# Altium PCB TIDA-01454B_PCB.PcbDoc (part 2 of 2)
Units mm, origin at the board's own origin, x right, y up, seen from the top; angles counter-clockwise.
Board outline 75 x 75 mm, 6 copper layers (Top Copper, Copper Layer 2, Copper Layer 3, Copper Layer 4, Copper Layer 5, Bottom Copper), stack 1.56 mm thick; 207 components, 118 nets, 481 pads, 110 vias.
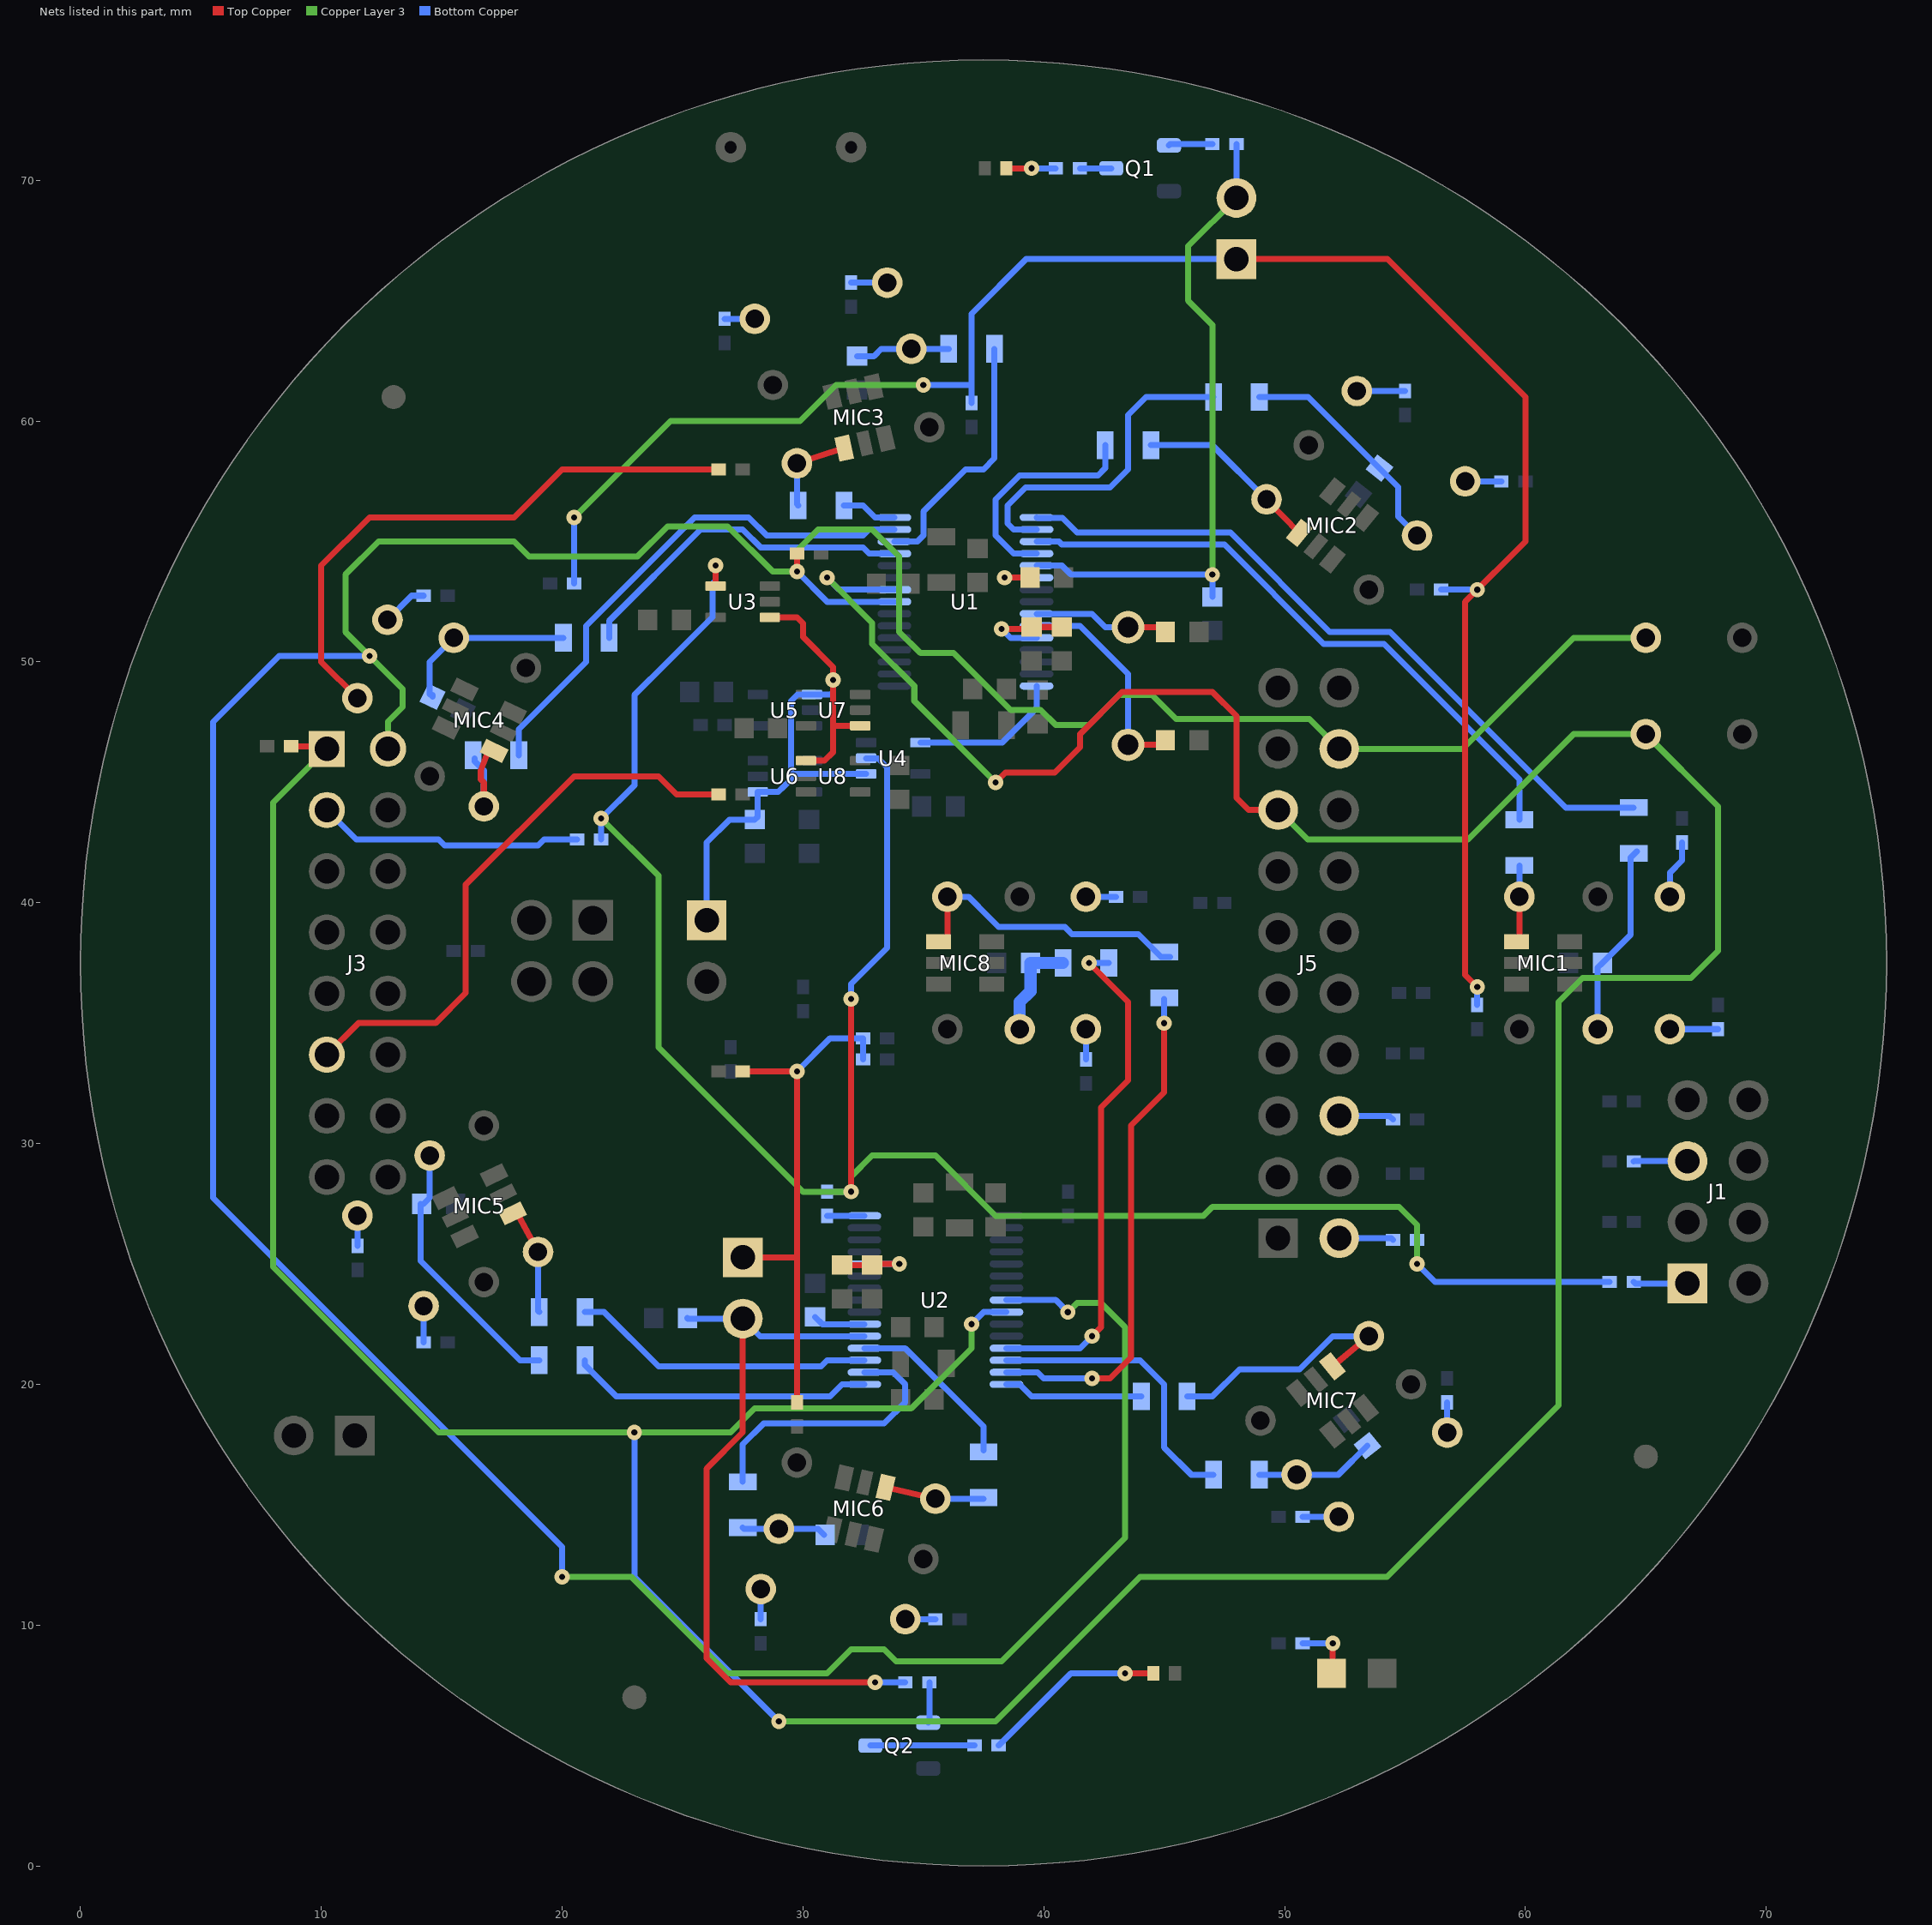
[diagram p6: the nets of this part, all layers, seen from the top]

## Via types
v1: diameter 0.635, hole 0.254, Top Copper to Bottom Copper, tented both sides, 98 vias
v2: diameter 0.762, hole 0.381, Top Copper to Bottom Copper, 7 vias
v3: diameter 6, hole 3.25, Top Copper to Bottom Copper, tented both sides, 4 vias
v4: diameter 0.75, hole 0.38, Top Copper to Bottom Copper, 1 vias

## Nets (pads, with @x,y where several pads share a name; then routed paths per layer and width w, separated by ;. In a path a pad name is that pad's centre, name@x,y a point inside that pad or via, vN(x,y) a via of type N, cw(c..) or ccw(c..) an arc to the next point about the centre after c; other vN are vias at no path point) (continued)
LRCLK-I2X: J3.11 R6.2 | length 24
  Top Copper w0.25: J3.11@10.23,33.69 11.54,35 14.75,35 16,36.25 16,40.75 20.5,45.25 24,45.25 24.75,44.5 R6.2@26.5,44.5
LRCLK-MINIDSP: J5.6 R16.2 | length 2.3
  Bottom Copper w0.25: J5.6@52.27,31.15 54.35,31.15 R16.2@54.5,31
LRCLK-PSIA: J1.5 R3.2 | length 2.2
  Bottom Copper w0.25: R3.2@64.5,29.25 64.52,29.27 J1.5@66.73,29.27
MCLK-I2X: J3.3 R9.2 | length 11.1
  Bottom Copper w0.25: J3.3@10.23,43.85 11.455,42.625 14.875,42.625 15.125,42.375 19,42.375 19.25,42.625 R9.2@20.625,42.625
MCLK-MINIDSP: J5.2 R12.2 | length 2.3
  Bottom Copper w0.25: J5.2@52.27,26.07 54.43,26.07 R12.2@54.5,26
MCLK-PSIA: J1.1 R1.2 | length 2.3
  Bottom Copper w0.25: R1.2@64.5,24.25 64.56,24.19 J1.1@66.73,24.19
MICBIAS-A: C23.2 J7.2 R47.2 U1.5 | length 27.5
  Copper Layer 3 w0.25: v1(47,53.625) 47,64 46,65 46,67.27 J7.2@48,69.27
  Bottom Copper w0.25: U1.5@39.7,54 40.75,54 41.125,53.625 v1(47,53.625) C23.2@47,52.7 ; J7.2@48,69.27 R47.2@48,71.5
MICBIAS-B: C37.2 J8.2 R58.2 U2.5 | length 31.1
  Top Copper w0.25: J8.2@27.5,22.73 27.5,18 26,16.5 26,8.625 27,7.625 v1(33,7.625)
  Bottom Copper w0.25: C37.2@25.2,22.75 25.22,22.73 J8.2@27.5,22.73 28.23,22 U2.5@32.55,22 ; v1(33,7.625) R58.2@34.25,7.625
NetC9_2: C9.2 MIC1.4 TP11.1 | length 3.2
  Top Copper w0.25: MIC1.4@59.634,38.384 59.75,38.5 TP11.1@59.75,40.25
  Bottom Copper w0.25: TP11.1@59.75,40.25 C9.2@59.75,41.55
NetC10_2: C10.2 MIC2.4 TP12.1 | length 7.7
  Top Copper w0.25: TP12.1@49.25,56.75 MIC2.4@50.609,55.356
  Bottom Copper w0.25: C10.2@44.45,59 47,59 TP12.1@49.25,56.75
NetC11_2: C11.2 MIC3.4 TP13.1 | length 3.8
  Top Copper w0.25: TP13.1@29.75,58.25 MIC3.4@31.713,58.882
  Bottom Copper w0.25: TP13.1@29.75,58.25 29.75,56.55 C11.2@29.8,56.5
NetC12_2: C12.2 MIC4.4 TP14.1 | length 5
  Top Copper w0.25: TP14.1@16.75,44 16.75,45 16.625,45.125 16.625,45.5 16.958,46.388 17,46.5 MIC4.4@17.174,46.307
  Bottom Copper w0.25: C12.2@16.375,46 16.375,45.875 16.75,45.5 TP14.1@16.75,44
NetC13_2: C13.2 R23.1 TP15.1 | length 8
  Bottom Copper w0.25: TP15.1@63,34.75 63,37.3 R23.1@63.2,37.5 64.375,38.675 64.375,41.875 C13.2@64.625,42.125
NetC14_2: C14.2 R24.1 TP16.1 | length 9.7
  Bottom Copper w0.25: C14.2@48.95,61 50.984,61 R24.1@53.936,58.047 54.718,57.266 54.718,56.032 TP16.1@55.5,55.25
NetC15_2: C15.2 R25.1 TP17.1 | length 3.9
  Bottom Copper w0.25: R25.1@32.25,62.7 32.95,62.7 33.25,63 TP17.1@34.5,63 C15.2@36.05,63
NetC16_2: C16.2 R26.1 TP18.1 | length 7.5
  Bottom Copper w0.25: R26.1@14.619,48.619 R26.1@14.619,48.554 14.5,48.673 14.5,50 TP18.1@15.5,51 C16.2@20.05,51
NetC19_2: C19.2 MIC5.4 TP35.1 | length 4.6
  Top Copper w0.25: MIC5.4@17.942,27.099 18.125,27.125 TP35.1@19,25.5
  Bottom Copper w0.25: TP35.1@19,25.5 19,23.05 C19.2@19.05,23
NetC20_2: C20.2 MIC6.4 TP36.1 | length 4.1
  Top Copper w0.25: MIC6.4@33.437,15.724 TP36.1@35.5,15.25
  Bottom Copper w0.25: TP36.1@35.5,15.25 C20.2@37.5,15.25
NetC21_2: C21.2 MIC7.4 TP37.1 | length 10.5
  Top Copper w0.25: MIC7.4@51.992,20.747 TP37.1@53.5,22
  Bottom Copper w0.25: C21.2@45.95,19.5 47,19.5 48.125,20.625 50.625,20.625 52,22 TP37.1@53.5,22
NetC22_2: C22.2 MIC8.4 TP38.1 | length 12.5
  Top Copper w0.25: MIC8.4@35.634,38.384 35.991,38.384 36,38.375 TP38.1@36,40.25
  Bottom Copper w0.25: TP38.1@36,40.25 36.875,40.25 37.75,39.375 38.125,39 40.875,39 41,38.875 41.175,38.7 43.925,38.7 44.875,37.75 C22.2@45.25,37.75
NetC24_1: C24.1 U1.6 | length 2.4
  Top Copper w0.25: v1(38.375,53.5) C24.1@39.425,53.5 C24.1@39.5,53.5
  Bottom Copper w0.25: v1(38.375,53.5) U1.6@39.7,53.5
NetC25_2: C25.2 C26.1 U1.11 | length 4.1
  Top Copper w0.25: v1(38.25,51.375) 39.425,51.375 C25.2@39.5,51.45 C26.1@40.75,51.45
  Bottom Copper w0.25: v1(38.25,51.375) 38.625,51 U1.11@39.7,51
NetC27_1: C27.1 U1.9 Y1.1 | length 5.6
  Top Copper w0.25: Y1.1@43.5,51.44 44.81,51.44 C27.1@45,51.25
  Bottom Copper w0.25: U1.9@39.7,52 42,52 42.56,51.44 Y1.1@43.5,51.44
NetC28_1: C28.1 U1.10 Y1.2 | length 9.6
  Top Copper w0.25: Y1.2@43.5,46.56 44.81,46.56 C28.1@45.25,47
  Bottom Copper w0.25: U1.10@39.7,51.5 41.5,51.5 43.5,49.5 Y1.2@43.5,46.56 Y1.2@43.5,46.5
NetC33_2: C33.2 R32.1 TP39.1 | length 11.1
  Bottom Copper w0.25: R32.1@14.125,27.5 14.125,25.125 18.25,21 C33.2@19.05,21 ; R32.1@14.25,27.5 14.5,27.75 TP39.1@14.5,29.5
NetC34_2: C34.2 R33.1 TP40.1 | length 3.5
  Bottom Copper w0.25: C34.2@27.5,14.05 27.55,14 TP40.1@29,14 30.625,14 R33.1@30.875,13.75
NetC35_2: C35.2 R34.1 TP41.1 | length 5
  Bottom Copper w0.25: C35.2@48.95,16.25 TP41.1@50.5,16.25 52.234,16.25 R34.1@53.436,17.453
NetC36_2: C36.2 R35.1 TP42.1 | length 4.3
  Bottom Copper w0.5: TP42.1@39,34.75 39,35.875 39.45,36.325 R35.1@39.45,37.5 C36.2@40.8,37.5
NetC38_1: C38.1 U2.6 | length 2.2
  Bottom Copper w0.25: C38.1@30.5,22.8 30.8,22.5 U2.6@32.55,22.5
NetC39_2: C39.2 C40.1 U2.11 | length 3.8
  Top Copper w0.25: C40.1@31.625,24.95 C39.2@32.875,24.95 32.925,25 v1(34,25)
  Bottom Copper w0.25: U2.11@32.55,25 v1(34,25)
NetD1_1: D1.1 R18.1 | length 2.5
  Top Copper w0.25: D1.1@52,7.95 v1(52,9.25)
  Bottom Copper w0.25: R18.1@50.75,9.25 v1(52,9.25)
NetD2_2: D2.2 R20.1 | length 2
  Top Copper w0.25: D2.2@38.45,70.5 v1(39.5,70.5)
  Bottom Copper w0.25: v1(39.5,70.5) R20.1@40.5,70.5
NetD3_2: D3.2 R53.1 | length 8
  Top Copper w0.25: v1(43.375,8) D3.2@44.55,8
  Bottom Copper w0.25: R53.1@38.125,5 41.125,8 43.5,8 v1@43.375,7.875
NetJ2_1: J2.1 R5.1 U3.1 U4.1 U5.1 U6.1 U7.1 U8.1 | length 27.1
  Top Copper w0.25: U3.1@28.625,51.85 29.75,51.85 30,51.6 30,51.041 31.25,49.791 v1(31.25,49.25) 31.25,47.375 ; U8.1@30.125,45.9 30.9,45.9 31.25,46.25 31.25,47.375 ; U7.1@32.375,47.35 31.275,47.35 31.25,47.375
  Bottom Copper w0.25: J2.1@26,39.27 26,42.5 26.95,43.45 R5.1@28,43.45 28.125,43.575 U6.1@28.125,44.6 28.975,44.6 29.25,44.875 ; 29.125,44.75 29.5,45.125 29.5,45.375 ; v1(31.25,49.25) 31.25,48.75 31.15,48.65 U5.1@30.375,48.65 29.775,48.65 29.5,48.375 29.5,45.375 ; U4.1@32.625,45.35 29.525,45.35 29.5,45.375
NetJ7_1: J7.1 R27.1 R28.1 R29.1 R30.1 | length 79.5
  Top Copper w0.25: J7.1@48,66.73 54.27,66.73 60,61 60,55 57.5,52.5 57.5,37 v1(58,36.5)
  Copper Layer 3 w0.25: v1(20.5,56) 24.5,60 29.875,60 31.375,61.5 v1(35,61.5)
  Bottom Copper w0.25: R30.1@20.5,53.25 v1(20.5,56) ; v1(35,61.5) 37,61.5 ; R29.1@37,60.75 37,61.5 ; J7.1@48,66.73 39.271,66.73 37,64.459 37,61.5 ; R28.1@56.5,53 v1(58,53) ; R27.1@58,35.75 v1(58,36.5)
NetJ8_1: J8.1 R36.1 R37.1 R38.1 R39.1 | length 22.5
  Top Copper w0.25: J8.1@27.5,25.27 29.73,25.27 29.75,25.25 ; R36.1@27.5,33 v1(29.75,33) 29.75,25.25 ; R37.1@29.75,19.25 29.75,25.25
  Bottom Copper w0.25: v1(29.75,33) 31.125,34.375 R39.1@32.5,34.375 R38.1@32.5,33.5
NetQ1_1: Q1.1 R47.1 | length 1.8
  Bottom Copper w0.25: Q1.1@45.2,71.45 45.25,71.5 R47.1@47,71.5
NetQ1_3: Q1.3 R20.2 | length 1.3
  Bottom Copper w0.25: R20.2@41.5,70.5 Q1.3@42.8,70.5
NetQ2_1: Q2.1 R58.1 | length 1.7
  Bottom Copper w0.25: Q2.1@35.2,5.95 35.25,6 R58.1@35.25,7.625
NetQ2_3: Q2.3 R53.2 | length 4.3
  Bottom Copper w0.25: Q2.3@32.8,5 R53.2@37.125,5
NetR40_2: R40.2 TP19.1 | length 2.5
  Bottom Copper w0.25: TP19.1@66,40.25 66,41.25 66.5,41.75 R40.2@66.5,42.5
NetR41_2: R41.2 TP20.1 | length 2
  Bottom Copper w0.25: TP20.1@53,61.25 R41.2@55,61.25
NetR42_2: R42.2 TP21.1 | length 1.3
  Bottom Copper w0.25: R42.2@26.75,64.25 TP21.1@28,64.25
NetR43_2: R43.2 TP22.1 | length 24.3
  Top Copper w0.25: TP22.1@11.5,48.5 10,50 10,54 12,56 18,56 20,58 R43.2@26.5,58
NetR49_2: R49.2 TP23.1 | length 2
  Bottom Copper w0.25: TP23.1@66,34.75 R49.2@68,34.75
NetR50_2: R50.2 TP24.1 | length 1.5
  Bottom Copper w0.25: TP24.1@57.5,57.5 R50.2@59,57.5
NetR51_2: R51.2 TP25.1 | length 1.5
  Bottom Copper w0.25: R51.2@32,65.75 TP25.1@33.5,65.75
NetR52_2: R52.2 TP26.1 | length 1.9
  Bottom Copper w0.25: TP26.1@12.75,51.75 13.75,52.75 R52.2@14.25,52.75
NetR54_2: R54.2 TP44.1 | length 1.5
  Bottom Copper w0.25: R54.2@14.25,21.75 TP44.1@14.25,23.25
NetR55_2: R55.2 TP45.1 | length 1.2
  Bottom Copper w0.25: TP45.1@34.25,10.25 R55.2@35.5,10.25
NetR56_2: R56.2 TP46.1 | length 1.3
  Bottom Copper w0.25: TP46.1@56.75,18 R56.2@56.75,19.25
NetR57_2: R57.2 TP43.1 | length 1.2
  Bottom Copper w0.25: TP43.1@41.75,40.25 R57.2@43,40.25
NetR59_2: R59.2 TP48.1 | length 1.2
  Bottom Copper w0.25: R59.2@11.5,25.75 TP48.1@11.5,27
NetR60_2: R60.2 TP49.1 | length 1.2
  Bottom Copper w0.25: R60.2@28.25,10.25 TP49.1@28.25,11.5
NetR61_2: R61.2 TP50.1 | length 1.5
  Bottom Copper w0.25: R61.2@50.75,14.5 TP50.1@52.25,14.5
NetR62_2: R62.2 TP47.1 | length 1.2
  Bottom Copper w0.25: R62.2@41.75,33.5 TP47.1@41.75,34.75
SCK: R1.1 R9.1 R10.2 R12.1 U3.4 U4.2 | length 92.4
  Top Copper w0.25: U3.4@26.375,53.15 v1(26.375,54) ; v1(32,28) v1(32,36)
  Copper Layer 3 w0.25: v1(21.625,43.5) 24,41.125 24,34 30,28 v1(32,28) 32,28.625 32.875,29.5 35.5,29.5 38,27 46.625,27 47,27.375 54.75,27.375 55.5,26.625 v1(55.5,25)
  Bottom Copper w0.25: R9.1@21.625,42.625 v1(21.625,43.5) 23,44.875 23,48.625 24.375,50 26.25,51.875 26.25,53.25 26.375,53.375 v1(26.375,54) ; R10.2@31,28 v1(32,28) ; v1(32,36) 32,36.625 33.5,38.125 33.5,45.625 33.125,46 U4.2@32.625,46 ; R12.1@55.5,26 v1(55.5,25) 56.25,24.25 R1.1@63.5,24.25
SCKIA: U1.15 U4.4 | length 6.3
  Bottom Copper w0.25: U4.4@34.875,46.65 38.275,46.65 39.7,48.075 U1.15@39.7,49
SCKIB: R10.1 U2.15 | length 1.6
  Bottom Copper w0.25: R10.1@31,27 U2.15@32.55,27
SCL: J3.1 J5.15 R14.2 TP3.1 U1.24 U2.24 | length 196.3
  Top Copper w0.25: R14.2@8.75,46.5 10.12,46.5 J3.1@10.23,46.39 ; v1(38,45) 38.409,45.409 40.45,45.409 41.5,46.459 41.5,47 43.25,48.75 47,48.75 48,47.75 48,44.35 48.5,43.85 J5.15@49.73,43.85
  Copper Layer 3 w0.25: J3.1@10.23,46.39 8,44.16 8,24.875 14.875,18 v1(23,18) 27,18 28,19 34.5,19 37,21.5 v1(37,22.5) ; v1(29,6) 38,6 44,12 54.25,12 61.375,19.125 61.375,35.875 62.375,36.875 66.875,36.875 68,38 68,44 TP3.1@65,47 62,47 57.625,42.625 50.955,42.625 J5.15@49.73,43.85 ; v1(31,53.5) 32.875,51.625 32.875,50.75 34.625,49 34.625,48.375 v1(38,45)
  Bottom Copper w0.25: v1(23,18) 23,12 v1(29,6) ; v1(31,53.5) 31.5,53 U1.24@33.8,53 ; v1(37,22.5) 37.5,23 U2.24@38.45,23
SDA: J3.2 J5.18 R15.2 TP4.1 U1.23 U2.23 | length 171.1
  Top Copper w0.25: v1(29.75,53.75) R15.2@29.75,54.5
  Copper Layer 3 w0.25: J3.2@12.77,46.39 12.77,47.52 13.375,48.125 13.375,48.875 11,51.25 11,53.625 12.375,55 18,55 18.625,54.375 23.125,54.375 24.375,55.625 26.875,55.625 28.75,53.75 v1(29.75,53.75) 29.75,54.625 30.625,55.5 32.875,55.5 34,54.375 34,51.25 34.875,50.375 36.25,50.375 38.625,48 39.875,48 40.5,47.375 41.875,47.375 43.125,48.625 44.5,48.625 45.5,47.625 51.035,47.625 J5.18@52.27,46.39 57.39,46.39 62,51 TP4.1@65,51 ; v1(20,12) 22.875,12 26.875,8 31,8 32,9 33.375,9 33.875,8.5 38.25,8.5 43.375,13.625 43.375,22.375 42.375,23.375 41.375,23.375 v1(41,23)
  Bottom Copper w0.25: v1(12,50.25) 8.25,50.25 5.5,47.5 5.5,27.75 20,13.25 v1(20,12) ; v1(29.75,53.75) 31,52.5 U1.23@33.8,52.5 ; U2.23@38.45,23.5 40.5,23.5 v1(41,23)
VIN1M: C13.1 U1.1 | length 29.8
  Bottom Copper w0.25: U1.1@39.7,56 39.725,55.975 40.775,55.975 41.375,55.375 47.75,55.375 51.875,51.25 54.375,51.25 61.675,43.95 C13.1@64.5,43.95
VIN1P: C9.1 U1.3 | length 25.8
  Bottom Copper w0.25: U1.3@39.7,55 40.625,55 40.75,54.875 47.5,54.875 51.625,50.75 54.125,50.75 59.75,45.125 C9.1@59.75,43.45
VIN2M: C14.1 U1.2 | length 13.8
  Bottom Copper w0.25: U1.2@39.7,55.5 38.75,55.5 38.5,55.75 38.5,56.5 39.25,57.25 42.75,57.25 43.5,58 43.5,60.25 44.25,61 C14.1@47.05,61
VIN2P: C10.1 U1.4 | length 9.5
  Bottom Copper w0.25: U1.4@39.7,54.5 38.75,54.5 38,55.25 38,56.75 39,57.75 42.25,57.75 42.55,58.05 C10.1@42.55,59
VIN3M: C15.1 U1.28 | length 10.7
  Bottom Copper w0.25: U1.28@33.8,55 34.75,55 35,55.25 35,56.25 36.75,58 37.5,58 37.95,58.45 C15.1@37.95,63
VIN3P: C11.1 U1.30 | length 2.3
  Bottom Copper w0.25: C11.1@31.7,56.5 32.5,56.5 33,56 U1.30@33.8,56
VIN4M: C16.1 U1.27 | length 14.5
  Bottom Copper w0.25: C16.1@21.95,51 21.95,51.7 25.75,55.5 27.5,55.5 28.25,54.75 32.5,54.75 32.75,54.5 U1.27@33.8,54.5
VIN4P: C12.1 U1.29 | length 21.6
  Bottom Copper w0.25: C12.1@18.2,46.125 18.2,47.2 21,50 21,51.5 25.5,56 27.75,56 28.5,55.25 32.5,55.25 32.75,55.5 U1.29@33.8,55.5
VIN5M: C33.1 U2.1 | length 12.5
  Bottom Copper w0.25: C33.1@20.95,21 20.95,20.8 22.25,19.5 31.125,19.5 31.625,20 U2.1@32.55,20
VIN5P: C19.1 U2.3 | length 12.6
  Bottom Copper w0.25: C19.1@20.95,23 21.75,23 24,20.75 30.75,20.75 31,21 U2.3@32.55,21
VIN6M: C34.1 U2.2 | length 11.7
  Bottom Copper w0.25: C34.1@27.5,15.95 27.5,17.5 28.375,18.375 33.375,18.375 34.25,19.25 34.25,20 33.75,20.5 U2.2@32.55,20.5
VIN6P: C20.1 U2.4 | length 7.3
  Bottom Copper w0.25: U2.4@32.55,21.5 34.25,21.5 37.5,18.25 C20.1@37.5,17.25
VIN7M: C35.1 U2.28 | length 12.1
  Bottom Copper w0.25: U2.28@38.45,21 44,21 45,20 45,17.375 46.125,16.25 C35.1@47.05,16.25
VIN7P: C21.1 U2.30 | length 5.8
  Bottom Copper w0.25: U2.30@38.45,20 39,20 39.5,19.5 C21.1@44.05,19.5
VIN8M: C36.1 U2.27 | length 21.4
  Top Copper w0.25: v1(41.875,37.5) 43.5,35.875 43.5,32.625 42.375,31.5 42.375,22.375 v1(42,22)
  Bottom Copper w0.25: U2.27@38.45,21.5 41.5,21.5 v1(42,22) ; v1(41.875,37.5) C36.1@42.7,37.5
VIN8P: C22.1 U2.29 | length 21.1
  Top Copper w0.25: v1(42,20.25) 42.75,20.25 43.625,21.125 43.625,30.75 45,32.125 v1(45,35)
  Bottom Copper w0.25: U2.29@38.45,20.5 39.75,20.5 40,20.25 v1(42,20.25) ; v1(45,35) C22.1@45,36
pads on no net: FID1.1 FID2.1 FID3.1 H1.0 H2.0 H3.0 H4.0 H5.0 H6.0 H7.0 H8.0 J3.5 J3.13 J3.14 SH1.0 SH2.0 SH3.0 SH4.0 U1.26 U2.9 U2.10 U2.26

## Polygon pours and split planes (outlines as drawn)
GND on Copper Layer 4 "GND Copper Layer 4" (solid, remove dead copper, pour order 10): 37.5,74.5 ccw(c37.5,37.5) 0.5,37.5 ccw(c37.5,37.5) 37.5,0.5 ccw(c37.5,37.5) 74.5,37.5 ccw(c37.5,37.5)
3.3V on Copper Layer 4 "3.3V Copper Layer 4" (solid, remove dead copper, pour order 0): 6,26.875 6,48 25.625,67.625 50.375,67.625 56,62 56,15 45,4 28.875,4
GND on Top Copper "GND Top Copper" (solid, remove dead copper, pour order 2): 37.5,74.5 ccw(c37.5,37.5) 0.5,37.5 ccw(c37.5,37.5) 37.5,0.5 ccw(c37.5,37.5) 74.5,37.5 ccw(c37.5,37.5)
GND on Copper Layer 2 "GND Copper Layer 2" (solid, remove dead copper, pour order 6): 37.5,74.5 ccw(c37.5,37.5) 0.5,37.5 ccw(c37.5,37.5) 37.5,0.5 ccw(c37.5,37.5) 74.5,37.5 ccw(c37.5,37.5)
GND on Copper Layer 5 "GND Copper Layer 5" (solid, remove dead copper, pour order 4): 37.5,74.5 ccw(c37.5,37.5) 0.5,37.5 ccw(c37.5,37.5) 37.5,0.5 ccw(c37.5,37.5) 74.5,37.5 ccw(c37.5,37.5)
GND on Copper Layer 3 "GND Copper Layer 3" (solid, remove dead copper, pour order 12): 37.5,74.5 ccw(c37.5,37.5) 0.5,37.5 ccw(c37.5,37.5) 37.5,0.5 ccw(c37.5,37.5) 74.5,37.5 ccw(c37.5,37.5)
GND on Bottom Copper "GND Bottom Copper" (solid, remove dead copper, pour order 8): 37.5,74.5 ccw(c37.5,37.5) 0.5,37.5 ccw(c37.5,37.5) 37.5,0.5 ccw(c37.5,37.5) 74.5,37.5 ccw(c37.5,37.5)

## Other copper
Top Copper:
  text ".Layer_Name" at 2.156,-34.306 h1.52
Copper Layer 2:
  text ".Layer_Name" at 2.156,-34.306 h1.52
Copper Layer 3:
  text ".Layer_Name" at 2.156,-34.306 h1.52
Copper Layer 4:
  text ".Layer_Name" at 2.156,-34.306 h1.52
Copper Layer 5:
  text ".Layer_Name" at 2,-34.25 h1.52
Bottom Copper:
  text ".Layer_Name" at 2.156,-34.306 h1.52

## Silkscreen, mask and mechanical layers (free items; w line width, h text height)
Top SilkScreen:
  circle w0.254: c64.5,57.625 r3.25
  circle w0.254: c15.5,12 r3.25
  circle w0.254: c60.875,13.125 r3.25
  circle w0.254: c17.5,64.75 r3.25
  lines w0.2: 47.75,26.18 48.5,26.18 ; 47.75,28.72 48.5,28.72 ; 47.75,31.26 48.5,31.26 ; 47.75,33.8 48.5,33.8 ; 47.75,36.34 48.5,36.34 ; 47.75,38.88 48.5,38.88 ; 47.75,41.42 48.5,41.42 ; 47.75,46.5 48.5,46.5 ; 47.875,25.93 48.375,25.93 ; 47.875,28.47 48.375,28.47 ; 47.875,31.01 48.375,31.01 ; 47.875,33.55 48.375,33.55 ; 47.875,36.09 48.375,36.09 ; 47.875,38.63 48.375,38.63 ; 47.875,41.17 48.375,41.17 ; 47.875,46.25 48.375,46.25 ; 48,25.68 48.25,25.68 ; 48,28.22 48.25,28.22 ; 48,30.76 48.25,30.76 ; 48,33.3 48.25,33.3 ; 48,35.84 48.25,35.84 ; 48,38.38 48.25,38.38 ; 48,40.92 48.25,40.92 ; 48,46 48.25,46 ; 48.125,26.18 48.125,26.555 ; 48.125,28.72 48.125,29.095 ; 48.125,31.26 48.125,31.635 ; 48.125,33.8 48.125,34.175 ; 48.125,36.34 48.125,36.715 ; 48.125,38.88 48.125,39.255 ; 48.125,41.42 48.125,41.795 ; 48.125,46.5 48.125,46.875
  text "PCM1864CMB" at 8.25,57.25 h1.8
  text "'.PRJ_Number' '.PCB_Rev'" at 8.25,55 h1.5
  text "INTB" at 45.875,48.375 h1
  text "INTA" at 53.5,48.375 h1
  text "SDA" at 53.5,45.875 h1
  text "SCL" at 46,43.25 h1
  text "3.3V" at 53.5,43.25 h1
  text "DATA4" at 53.5,40.875 h1
  text "DATA3" at 53.5,38.25 h1
  text "DATA2" at 53.5,35.75 h1
  text "DATA1" at 53.5,33.125 h1
  text "LRCLK" at 53.5,30.5 h1
  text "BCLK" at 53.5,28.125 h1
  text "MCLK" at 53.5,25.625 h1
  text ".Layer_Name" at 2.156,-34.306 h1.52
Bottom Silk:
  lines w0.2: 47.23,26.235 47.98,26.235 ; 47.23,28.775 47.98,28.775 ; 47.23,31.315 47.98,31.315 ; 47.23,33.855 47.98,33.855 ; 47.23,36.395 47.98,36.395 ; 47.23,38.935 47.98,38.935 ; 47.23,46.555 47.98,46.555 ; 47.355,25.985 47.855,25.985 ; 47.355,28.525 47.855,28.525 ; 47.355,31.065 47.855,31.065 ; 47.355,33.605 47.855,33.605 ; 47.355,36.145 47.855,36.145 ; 47.355,38.685 47.855,38.685 ; 47.355,46.305 47.855,46.305 ; 47.48,25.735 47.73,25.735 ; 47.48,28.275 47.73,28.275 ; 47.48,30.815 47.73,30.815 ; 47.48,33.355 47.73,33.355 ; 47.48,35.895 47.73,35.895 ; 47.48,38.435 47.73,38.435 ; 47.48,46.055 47.73,46.055 ; 47.605,26.235 47.605,26.61 ; 47.605,28.775 47.605,29.15 ; 47.605,31.315 47.605,31.69 ; 47.605,33.855 47.605,34.23 ; 47.605,36.395 47.605,36.77 ; 47.605,38.935 47.605,39.31 ; 47.605,46.555 47.605,46.93
  text "INTA" at 56.75,48.25 h1
  text "INTB" at 47,47.625 h1 r270
  text "SDA" at 56.625,45.75 h1
  text "3.3V" at 56.875,43.25 h1
  text "SCL" at 48,43.125 h1
  text "D1A" at 19.875,41.25 h1
  text "DATA4" at 58.25,40.5 h1
  text "DATA3" at 58.375,38.25 h1
  text "MASTER/ / SLAVE" at 34.125,37.125 h1
  text "DATA1" at 23,36 h1 r270
  text "D2" at 55.625,34.625 h1
  text "D1B" at 19.875,33.75 h1
  text "DATA" at 65,32.5 h1
  text "D1" at 55.375,32 h1
  text "LRCLK" at 65,30 h1
  text "LRCLK" at 57.875,29.5 h1
  text "BCLK" at 65,27.5 h1
  text "BCLK" at 57.375,27 h1
  text "GND" at 71,26.875 h1 r270
  text "MCLK" at 65,24.875 h1
  text "MCLK" at 57.5,24.25 h1
  text ".Layer_Name" at 2.156,-34.306 h1.52
Top Paste:
  text ".Layer_Name" at 2.156,-34.306 h1.52
Bottom Paste:
  text ".Layer_Name" at 2.156,-34.306 h1.52
Top Solder Mask:
  text ".Layer_Name" at 2.156,-34.306 h1.52
Bottom Solder Mask:
  text ".Layer_Name" at 2.156,-34.306 h1.52
Drill Guide:
  text ".Layer_Name" at 80,36 h1.52
M1 Board Outline:
  circle w0.254: c37.5,37.5 r37.5
  text ".Layer_Name" at 44.25,-34.75 h1.52
M2 Board Dimensions:
  lines w0.2: 10,38 13.5,38 ; 12.5,37.5 13.5,38 ; 12.5,38.5 13.5,38
  text ".Layer_Name" at 69.75,-34.75 h1.52
M3 3D STEP Top:
  text ".Layer_Name" at 2.156,-34.306 h1.52
M4 3D STEP Bottom:
  text ".Layer_Name" at 2.156,-34.306 h1.52
M5 Assembly Top:
  circle w0.254: c37.5,37.5 r24
  lines w0.254: -19.917,-36.126 147.723,-36.126 ; -19.917,-30.962 147.774,-30.962 ; -19.917,-25.797 -19.917,-41.291 81.81,-41.291 147.774,-41.291 147.774,-25.797 -19.904,-25.797 -19.904,-41.291 20.114,-41.291 ; 42.694,-41.291 42.694,-25.797 ; 74.876,-30.962 74.876,-25.797 ; 96.212,-30.962 96.212,-25.797 ; 112.011,-41.456 112.011,-36.304
  text "PCB VIEWED FROM TOP SIDE" at -18.304,-29.154 h1.52
  text "BOARD #:" at 44.599,-29.154 h1.52
  text ".PRJ_Number" at 58.455,-29.154 h1.52
  text "REV:" at 79.905,-29.154 h1.52
  text ".PCB_Rev" at 87.309,-29.154 h1.52
  text "SVN REV:" at 101.19,-29.154 h1.52
  text ".VersionControl_RevNumber" at 114.043,-29.154 h1.52
  text "PLOT NAME =" at -18.304,-39.534 h1.52
  text ".plot_File_Name" at 2.156,-39.534 h1.52
  text "GENERATED    :" at 44.65,-39.534 h1.52
  text ".Print_Date" at 66.735,-39.534 h1.52
  text ".Print_Time" at 85.252,-39.534 h1.52
  text "TEXAS INSTRUMENTS" at 117.37,-39.534 h1.52
M6 Assembly Bottom:
  lines w0.254: -19.93,-30.974 147.761,-30.974 ; -19.879,-36.139 147.761,-36.139 ; 15.834,-41.469 15.834,-36.317 ; 31.632,-30.974 31.632,-25.81 ; 52.968,-30.974 52.968,-25.81 ; 85.15,-41.304 85.15,-25.81 ; 107.731,-41.304 147.749,-41.304 147.749,-25.81 -19.93,-25.81 -19.93,-41.304 46.034,-41.304 147.761,-41.304 147.761,-25.81
  text ".VersionControl_RevNumber" at 13.802,-29.167 h1.52
  text "SVN REV:" at 26.654,-29.167 h1.52
  text ".PCB_Rev" at 40.535,-29.167 h1.52
  text "REV:" at 47.939,-29.167 h1.52
  text ".PRJ_Number" at 69.39,-29.167 h1.52
  text "BOARD #:" at 83.245,-29.167 h1.52
  text "PCB VIEWED FROM BOTTOM SIDE" at 146.148,-29.167 h1.52
  text "TEXAS INSTRUMENTS" at 10.474,-39.547 h1.52
  text ".Print_Time" at 42.593,-39.547 h1.52
  text ".Print_Date" at 61.109,-39.547 h1.52
  text "GENERATED    :" at 83.194,-39.547 h1.52
  text ".plot_File_Name" at 125.689,-39.547 h1.52
  text "PLOT NAME =" at 146.148,-39.547 h1.52
M9 Title Sheet:
  drawing of 57 lines, arcs and shapes, not listed
  text "1" at 6.292,191.627 h1.78
  text "2" at 69.682,191.627 h1.78
  text "3" at 132.911,191.627 h1.78
  text "4" at 196.58,191.627 h1.78
  text "5" at 260.055,191.627 h1.78
  text "6" at 323.682,191.627 h1.78
  text "A" at -23.079,162.595 h1.78
  text "A" at 352.841,162.595 h1.78
  text "B" at -23.079,102.143 h1.78
  text "B" at 352.841,102.143 h1.78
  text "C" at -23.079,41.818 h1.78
  text "C" at 352.841,41.818 h1.78
  text "PROJECT TITLE:" at 275.625,-5.452 h1.14
  text ".PRJ_Title" at 276.895,-8.838 h1.78
  text "DESIGNED FOR:" at 275.625,-13.097 h1.14
  text ".PRJ_Customer" at 276.895,-16.653 h1.78
  text "D" at -23.079,-18.38 h1.78
  text "D" at 352.841,-18.38 h1.78
  text "FILE NAME:" at 275.625,-20.717 h1.14
  text ".PCB_File_Name_No_Path" at 276.895,-23.765 h1.78
  text "Texas Instruments (TI) and/or its licensors do not warrant the accuracy or completeness of this specification" at 149.4,-27.876 h1.14
  text "ENGINEER:" at 275.625,-28.083 h1.14
  text "LAYOUT BY:" at 313.852,-28.083 h1.14
  text "or any information contained therein. TI and/or its licensors do not warrant that this design will meet" at 148.257,-30.737 h1.14
  text ".PRJ_Engineer" at 276.895,-32.02 h1.78
  text ".PCB_Layout" at 315.135,-32.02 h1.78
  text "the specifications, will be suitable for your application or fit for any particular purpose, or will operate in" at 148.257,-33.599 h1.14
  text "ALTIUM DESIGNER VERSION:" at 313.852,-35.957 h1.14
  text "an implementation. TI and/or its licensors do not warrant that the design is production worthy. You should" at 148.257,-36.461 h1.14
  text "completely validate and test your design implementation to confirm the system functionality for your application." at 149.4,-39.322 h1.14
  text ".print_Scale" at 276.895,-39.343 h1.78
  text ".Application_BuildNumber" at 315.135,-39.343 h1.78
  text "1" at 6.292,-44.593 h1.78
  text "2" at 69.682,-44.593 h1.78
  text "3" at 132.911,-44.593 h1.78
  text "4" at 196.58,-44.593 h1.78
  text "5" at 260.055,-44.593 h1.78
  text "6" at 323.682,-44.593 h1.78
M10 Fab Notes:
  drawing of 185 lines, arcs and shapes, not listed
  text ".Layer_Name" at 274.75,186.75 h1.52
  text "SPECIAL NOTES" at 302.5,182.25 h2
  text "THE MICROPHONES USED IN THIS BOARD REQUIRE SPECIAL SOLDERING CONSIERATIONS:" at 275.5,175.5 h1.52
  text "MSL (MOISTURE SENSITIVITY LEVEL) CLASS 1. / MAXIMUM OF 3 REFLOW CYCLES IS RECOMMENDED. / DO NOT EXPOSE THE MICROPHONES TO TEMP EXCEEDING 260 C / DO NOT BOARD WASH OR CLEAN AFTER THE REFLOW PROCESS. / DO NOT BRUSH BOARD WITH OR WITHOUT SOLVENTS AFTER THE REFLOW PROCESS. / DO NOT DIRECTLY EXPOSE TO ULTRASONIC PROCESSING, WELDING, OR CLEANING. / DO NOT APPLY OVER 30 PSI OF AIR PRESSURE INTO THE PORT HOLE." at 279.875,149.625 h1.52
  text "DESIGN INFORMATION" at 301.902,145.005 h1.52
  text "MIN. TRACK WIDTH:" at 285.53,140.433 h1.52
  text "8" at 313.374,140.433 h1.52
  text "MIL" at 317.305,140.433 h1.52
  text "MIN. CLEARANCE:" at 285.53,137.081 h1.52
  text "0.2" at 311.85,137.081 h1.52
  text "mm" at 317.305,137.081 h1.52
  text "MIN. VIA PAD SIZE:" at 285.53,133.728 h1.52
  text "24" at 312.613,133.728 h1.52
  text "MIL" at 317.305,133.728 h1.52
  text "0.05mm (2MIL)" at 303.183,130.128 h1.52
  text "MINIMUM ANNULAR RING" at 277.167,130.02 h1.52
  text "EXTERNAL" at 321.166,130.02 h1.52
  text "PER" at 282.247,127.022 h1.52
  text "IPC-D-275 CLASS 2 LEVEL C" at 287.835,127.022 h1.52
  text "MIL, HOLES" at 325.636,124.17 h1.52
  text "+/-" at 315.668,124.152 h1.52
  text "+/-" at 337.36,124.152 h1.52
  text "REGISTRATION TOLERANCES:" at 277.167,124.025 h1.52
  text "METAL" at 307.642,124.025 h1.52
  text "5" at 322.277,124.025 h1.52
  text "3" at 343.435,124.025 h1.52
  text "MIL" at 346.388,124.025 h1.52
  text "+/-" at 337.36,121.155 h1.52
  text "HOLE SIZE TOLERANCE (UNLESS OTHERWISE SPECIFIED):" at 277.167,121.028 h1.52
  text "3" at 343.435,121.028 h1.52
  text "MIL" at 346.388,121.028 h1.52
  text "MATERIAL:" at 275.268,115.708 h1.52
  text "FR-4 High Tg" at 300.324,112.143 h1.52
  text "FR-408" at 285.962,111.925 h1.52
  text "OTHER" at 323.757,111.925 h1.52
  text "X" at 296.389,111.833 h1.52
  text "62 MIL (1.6mm) +/-10%" at 294.092,107.792 h1.52
  text "THICKNESS:" at 277.167,107.684 h1.52
  text "X" at 290.837,107.684 h1.52
  text "OTHER" at 326.729,107.684 h1.52
  text "TOLERANCE:" at 277.167,103.67 h1.52
  text "X" at 298.486,103.67 h1.52
  text "ANSI IPC-6012 TYPE 3 CLASS 2" at 303.234,103.67 h1.52
  text "OTHER +/-" at 303.234,99.708 h1.52
  text "BOW & TWIST:" at 277.167,95.72 h1.52
  text "X" at 298.486,95.72 h1.52
  text "ANSI IPC-6012 TYPE 3 CLASS 2" at 303.234,95.72 h1.52
  text "OTHER +/-" at 303.234,91.694 h1.52
  text "DRILLING:" at 275.268,88.176 h1.52
  text "REFERENCE:" at 277.167,85.205 h1.52
  text "X" at 293.632,85.205 h1.52
  text "AS SHOWN" at 298.382,85.205 h1.52
  text "X" at 316.518,85.205 h1.52
  text "NC_DRILL FILES" at 319.998,85.205 h1.52
  text "PTH COPPER THICKNESS:" at 277.167,81.191 h1.52
  text "X" at 305.875,81.191 h1.52
  text "20-30 um" at 309.355,81.191 h1.52
  text "OTHER" at 327.567,81.191 h1.52
  text "BOARD FINISH:" at 275.268,77.153 h1.52
  text "SILKSCREEN:" at 279.211,74.156 h1.52
  text "X" at 303.31,74.156 h1.52
  text "TOP" at 306.51,74.156 h1.52
  text "X" at 316.264,74.156 h1.52
  text "BOTTOM" at 319.49,74.156 h1.52
  text "SILKSCREEN COLOR:" at 279.211,69.914 h1.52
  text "X" at 303.283,69.914 h1.52
  text "WHITE" at 306.51,69.914 h1.52
  text "OTHER" at 319.49,69.914 h1.52
  text "X" at 306.611,65.87 h1.52
  text "GREEN" at 309.838,65.87 h1.52
  text "OTHER" at 325.535,65.87 h1.52
  text "SOLDER RESIST COLOR:" at 279.211,65.596 h1.52
  text "X" at 306.611,61.552 h1.52
  text "MATTE" at 309.838,61.552 h1.52
  text "SEMI-GLOSS" at 325.523,61.536 h1.52
  text "IMMERSION GOLD (ENIG)" at 302.218,56.764 h1.52
  text "ENEPIG" at 336.191,56.68 h1.52
  text "SURFACE FINISH:" at 275.268,56.655 h1.52
  text "X" at 297.469,56.655 h1.52
  text "IMM. TIN/SILVER OR EQUIV" at 283.639,52.667 h1.52
  text "OTHER" at 319.998,52.667 h1.52
  text "ARRAY/PANEL:" at 275.268,48.121 h1.52
  text "CUT AND TRIM PER M1 BOARD OUTLINE" at 302.218,48.012 h1.52
  text "N.C. ROUTE" at 302.218,44.158 h1.52
  text "X" at 319.464,44.158 h1.52
  text "V. SCORE" at 324.214,44.158 h1.52
  text "CERTIFICATION:" at 275.268,40.678 h1.52
  text "MATERIALS AND WORKMANSHIP FOR ALL PCBS" at 293.683,40.678 h1.52
  text "TO MEET OR EXCEED THE REQUIREMENTS OF:" at 293.683,38.189 h1.52
  text "X" at 284.196,34.722 h1.52
  text "ANSI IPC-A-600F CLASS ->" at 287.727,34.722 h1.52
  text "X" at 329.359,34.722 h1.52
  text "2" at 332.38,34.722 h1.52
  text "1" at 324.379,34.684 h1.52
  text "3" at 341.372,34.684 h1.52
  text "X" at 304.873,30.671 h1.52
  text "RoHS" at 308.352,30.671 h1.52
  text "OTHER" at 324.72,30.671 h1.52
  text "PER ORDER" at 334.805,30.671 h1.52
  text "ALL BOARDS MUST MEET OR EXCEED UL94-V0 REQUIREMENTS." at 275.968,26.464 h1.52
  text "PCB MUST BEAR THE UL94V-0 UL REGISTERED MATERIAL ID NUMBER" at 275.968,23.416 h1.52
  text "ADDITIONAL REQUIREMENTS:" at 275.268,19.012 h1.52
  text "MICROSECTION:" at 277.167,16.091 h1.52
  text "YES" at 300.173,16.091 h1.52
  text "REQUIRED" at 322.055,12.125 h1.52
  text "BARE BOARD ELEC. TEST:" at 277.167,12.053 h1.52
  text "NONE" at 310.333,12.053 h1.52
  text "X" at 318.829,12.053 h1.52
  text "PER ORDER" at 337.092,12.053 h1.52
M11 Gerber Information:
  lines w0.254: -19.917,-36.126 147.723,-36.126 ; -19.917,-30.962 147.774,-30.962 ; -19.917,-25.797 -19.917,-41.291 81.81,-41.291 147.774,-41.291 147.774,-25.797 -19.904,-25.797 -19.904,-41.291 20.114,-41.291 ; 42.694,-41.291 42.694,-25.797 ; 74.876,-30.962 74.876,-25.797 ; 96.212,-30.962 96.212,-25.797 ; 112.011,-41.456 112.011,-36.304
  text "ALL ARTWORK VIEWED FROM TOP SIDE" at -18.304,-29.154 h1.52
  text "BOARD #:" at 44.599,-29.154 h1.52
  text ".PRJ_Number" at 58.455,-29.154 h1.52
  text "REV:" at 79.905,-29.154 h1.52
  text ".PCB_Rev" at 87.309,-29.154 h1.52
  text "SVN REV:" at 101.19,-29.154 h1.52
  text ".VersionControl_RevNumber" at 114.043,-29.154 h1.52
  text "LAYER NAME =" at -18.304,-34.306 h1.52
  text "PLOT NAME =" at -18.304,-39.534 h1.52
  text ".plot_File_Name" at 2.156,-39.534 h1.52
  text "GENERATED    :" at 44.65,-39.534 h1.52
  text ".Print_Date" at 66.735,-39.534 h1.52
  text ".Print_Time" at 85.252,-39.534 h1.52
  text "TEXAS INSTRUMENTS" at 117.37,-39.534 h1.52
M12 Stackup:
  drawing of 399 lines, arcs and shapes, not listed
  text ".Layer_Name" at 80,90 h1.52
  text "Layer" at 81.715,86.672 h1.52
  text "Name" at 92.126,86.672 h1.52
  text "Material" at 121.582,86.672 h1.52
  text "Thickness" at 143.42,86.672 h1.52
  text "Constant" at 159.926,86.672 h1.52
  text "Board Layer Stack" at 174.4,86.672 h1.52
  text "1" at 81.715,83.624 h1.52
  text "Top SilkScreen" at 92.126,83.624 h1.52
  text "2" at 81.715,80.576 h1.52
  text "Top Solder Mask" at 92.126,80.576 h1.52
  text "Solder Resist" at 121.582,80.576 h1.52
  text "0.50mil" at 143.42,80.576 h1.52
  text "3.5" at 159.926,80.576 h1.52
  text "3" at 81.715,77.528 h1.52
  text "Top Copper" at 92.126,77.528 h1.52
  text "Copper" at 121.582,77.528 h1.52
  text "1.40mil" at 143.42,77.528 h1.52
  text "4" at 81.715,74.48 h1.52
  text "Dielectric 1" at 92.126,74.48 h1.52
  text "FR-4" at 121.582,74.48 h1.52
  text "7.00mil" at 143.42,74.48 h1.52
  text "4.2" at 159.926,74.48 h1.52
  text "5" at 81.715,71.432 h1.52
  text "Copper Layer 2" at 92.126,71.432 h1.52
  text "Copper" at 121.582,71.432 h1.52
  text "1.40mil" at 143.42,71.432 h1.52
  text "6" at 81.715,68.384 h1.52
  text "Dielectric 2" at 92.126,68.384 h1.52
  text "FR-4" at 121.582,68.384 h1.52
  text "14.00mil" at 143.42,68.384 h1.52
  text "4.2" at 159.926,68.384 h1.52
  text "7" at 81.715,65.336 h1.52
  text "Copper Layer 3" at 92.126,65.336 h1.52
  text "Copper" at 121.582,65.336 h1.52
  text "1.40mil" at 143.42,65.336 h1.52
  text "8" at 81.715,62.288 h1.52
  text "Dielectric 4" at 92.126,62.288 h1.52
  text "FR-4" at 121.582,62.288 h1.52
  text "11.00mil" at 143.42,62.288 h1.52
  text "4.2" at 159.926,62.288 h1.52
  text "9" at 81.715,59.24 h1.52
  text "Copper Layer 4" at 92.126,59.24 h1.52
  text "Copper" at 121.582,59.24 h1.52
  text "1.40mil" at 143.42,59.24 h1.52
  text "10" at 81.715,56.192 h1.52
  text "Dielectric 5" at 92.126,56.192 h1.52
  text "FR-4" at 121.582,56.192 h1.52
  text "14.00mil" at 143.42,56.192 h1.52
  text "4.2" at 159.926,56.192 h1.52
  text "11" at 81.715,53.144 h1.52
  text "Copper Layer 5" at 92.126,53.144 h1.52
  text "Copper" at 121.582,53.144 h1.52
  text "1.40mil" at 143.42,53.144 h1.52
  text "12" at 81.715,50.096 h1.52
  text "Dielectric 3" at 92.126,50.096 h1.52
  text "FR-4" at 121.582,50.096 h1.52
  text "7.00mil" at 143.42,50.096 h1.52
  text "4.2" at 159.926,50.096 h1.52
  text "13" at 81.715,47.048 h1.52
  text "Bottom Copper" at 92.126,47.048 h1.52
  text "Copper" at 121.582,47.048 h1.52
  text "1.40mil" at 143.42,47.048 h1.52
  text "14" at 81.715,44 h1.52
  text "Bottom Solder Mask" at 92.126,44 h1.52
  text "Solder Resist" at 121.582,44 h1.52
  text "0.50mil" at 143.42,44 h1.52
  text "3.5" at 159.926,44 h1.52
  text "15" at 81.715,40.952 h1.52
  text "Bottom Silk" at 92.126,40.952 h1.52
M13 Component Bodies Top:
  text ".Layer_Name" at 2.156,-34.306 h1.52
M14 Component Bodies Bottom:
  text ".Layer_Name" at 2.156,-34.306 h1.52
M15 Courtyards Top:
  text ".Layer_Name" at 2.156,-34.306 h1.52
M16 Courtyards Bottom:
  text ".Layer_Name" at 2.156,-34.306 h1.52
Drill Drawing:
  circle w0.254: c82.126,27.063 r0.702
  lines w0.254: 81.425,4.608 81.776,4.608 81.776,4.257 82.477,4.257 82.477,4.608 82.828,4.608 82.828,5.31 82.477,5.31 82.477,5.661 81.776,5.661 81.776,5.31 81.425,5.31 81.425,4.608 ; 81.425,7.415 82.126,7.766 82.828,7.415 82.477,8.117 82.828,8.819 82.126,8.468 81.425,8.819 81.776,8.117 81.425,7.415 ; 81.425,11.976 82.828,11.976 82.126,10.573 81.425,11.976 ; 81.425,14.081 81.776,14.081 82.126,13.731 82.477,14.081 82.828,14.081 82.477,14.432 82.828,14.783 82.477,14.783 82.126,15.134 81.776,14.783 81.425,14.783 81.776,14.432 81.425,14.081 ; 81.425,17.59 82.126,16.888 82.828,17.59 82.126,18.292 81.425,17.59 ; 81.425,20.046 81.425,20.397 81.776,20.748 81.425,21.099 81.425,21.45 81.776,21.45 82.126,21.099 82.477,21.45 82.828,21.45 82.828,21.099 82.477,20.748 82.828,20.397 82.828,20.046 82.477,20.046 82.126,20.397 81.776,20.046 81.425,20.046 ; 81.425,23.204 82.828,23.204 82.828,24.607 81.425,24.607 81.425,23.204 ; 81.425,29.519 82.828,29.519 82.828,30.923 81.425,30.923 81.425,29.519 ; 81.705,29.8 82.547,29.8 82.547,30.642 81.705,30.642 81.705,29.8
  lines w0.305: 80.152,3.31 164.499,3.31 ; 80.152,31.73 164.499,31.73 ; 88.734,0.152 88.734,34.887 ; 97.167,0.152 97.167,34.887 ; 113.336,0.152 113.336,34.887 ; 119.918,0.152 119.918,34.887 ; 129.447,0.152 129.447,34.887 ; 150.112,0.152 150.112,34.887 ; 80.152,0.152 164.499,0.152 164.499,34.887 80.152,34.887 80.152,0.152
  text "Symbol" at 82.047,32.677 h1.83
  text "Quantity" at 89.681,32.677 h1.83
  text "Finished Hole Size" at 98.114,32.677 h1.83
  text "Plated" at 114.283,32.677 h1.83
  text "Hole Type" at 120.865,32.677 h1.83
  text "Drill Layer Pair" at 130.394,32.677 h1.83
  text "Hole Tolerance" at 151.059,32.677 h1.83
  text "98" at 89.681,29.519 h1.52
  text "0.254mm (10.00mil)" at 98.114,29.519 h1.52
  text "PTH" at 114.283,29.519 h1.52
  text "Round" at 120.865,29.519 h1.52
  text "Top Copper - Bottom Copper" at 130.394,29.519 h1.52
  text "1" at 89.681,26.362 h1.52
  text "0.380mm (14.96mil)" at 98.114,26.362 h1.52
  text "PTH" at 114.283,26.362 h1.52
  text "Round" at 120.865,26.362 h1.52
  text "Top Copper - Bottom Copper" at 130.394,26.362 h1.52
  text "7" at 89.681,23.204 h1.52
  text "0.381mm (15.00mil)" at 98.114,23.204 h1.52
  text "PTH" at 114.283,23.204 h1.52
  text "Round" at 120.865,23.204 h1.52
  text "Top Copper - Bottom Copper" at 130.394,23.204 h1.52
  text "2" at 89.681,20.046 h1.52
  text "0.508mm (20.00mil)" at 98.114,20.046 h1.52
  text "PTH" at 114.283,20.046 h1.52
  text "Round" at 120.865,20.046 h1.52
  text "Top Copper - Bottom Copper" at 130.394,20.046 h1.52
  text "52" at 89.681,16.888 h1.52
  text "0.762mm (30.00mil)" at 98.114,16.888 h1.52
  text "PTH" at 114.283,16.888 h1.52
  text "Round" at 120.865,16.888 h1.52
  text "Top Copper - Bottom Copper" at 130.394,16.888 h1.52
  text "2" at 89.681,13.731 h1.52
  text "0.850mm (33.46mil)" at 98.114,13.731 h1.52
  text "PTH" at 114.283,13.731 h1.52
  text "Round" at 120.865,13.731 h1.52
  text "Top Copper - Bottom Copper" at 130.394,13.731 h1.52
  text "52" at 89.681,10.573 h1.52
  text "1.016mm (40.00mil)" at 98.114,10.573 h1.52
  text "PTH" at 114.283,10.573 h1.52
  text "Round" at 120.865,10.573 h1.52
  text "Top Copper - Bottom Copper" at 130.394,10.573 h1.52
  text "4" at 89.681,7.415 h1.52
  text "1.200mm (47.24mil)" at 98.114,7.415 h1.52
  text "PTH" at 114.283,7.415 h1.52
  text "Round" at 120.865,7.415 h1.52
  text "Top Copper - Bottom Copper" at 130.394,7.415 h1.52
  text "4" at 89.681,4.257 h1.52
  text "3.250mm (127.95mil)" at 98.114,4.257 h1.52
  text "PTH" at 114.283,4.257 h1.52
  text "Round" at 120.865,4.257 h1.52
  text "Top Copper - Bottom Copper" at 130.394,4.257 h1.52
  text "222 Total" at 89.681,1.1 h1.52
  text ".Layer_Name" at 2.156,-34.306 h1.52
Special Dims:
  circle w0.254: c37.5,37.5 r30
  circle w0.254: c37.5,37.5 r23.212
  circle w0.254: c37.5,37.5 r37.5
  lines w0.1: 17,47.372 23.25,44.362 ; 32.159,60.898 52.464,56.264
  lines w0.2: -6.5,37.5 81.5,37.5 ; 15.568,48.061 17.558,47.103 ; 15.569,26.938 17.558,27.896 ; 32.083,61.232 32.574,59.079 ; 32.084,13.768 32.576,15.921 ; 37.5,-0.5 37.5,87.5 ; 51.3,54.805 52.677,56.531 ; 51.301,20.196 52.678,18.469 ; 59.634,37.5 61.842,37.5
  lines w0.25: 15.877,27.086 37.5,37.5 ; 15.877,47.913 37.5,37.5 ; 32.159,60.898 37.5,37.5 ; 32.16,14.102 37.5,37.5 ; 52.464,56.264 37.5,37.5 ; 52.465,18.737 37.5,37.5 ; 61.5,37.5 37.5,37.5
  lines w0.254: 15.877,27.086 cw(c37.5,37.5) 15.877,47.913 ; 55.918,52.887 cw(c37.5,37.5) 60.161,45.405
  text "21.543mm" at -1.25,37.5 h1.25
  text ".Layer_Name" at 2.156,-34.306 h1.52

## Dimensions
37.5,37.5 to 63,50 on M16 Courtyards Bottom
52.464,56.264 to 32.159,60.898 on M16 Courtyards Bottom
37.5,37.5 to 9.369,9.369 on M1 Board Outline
